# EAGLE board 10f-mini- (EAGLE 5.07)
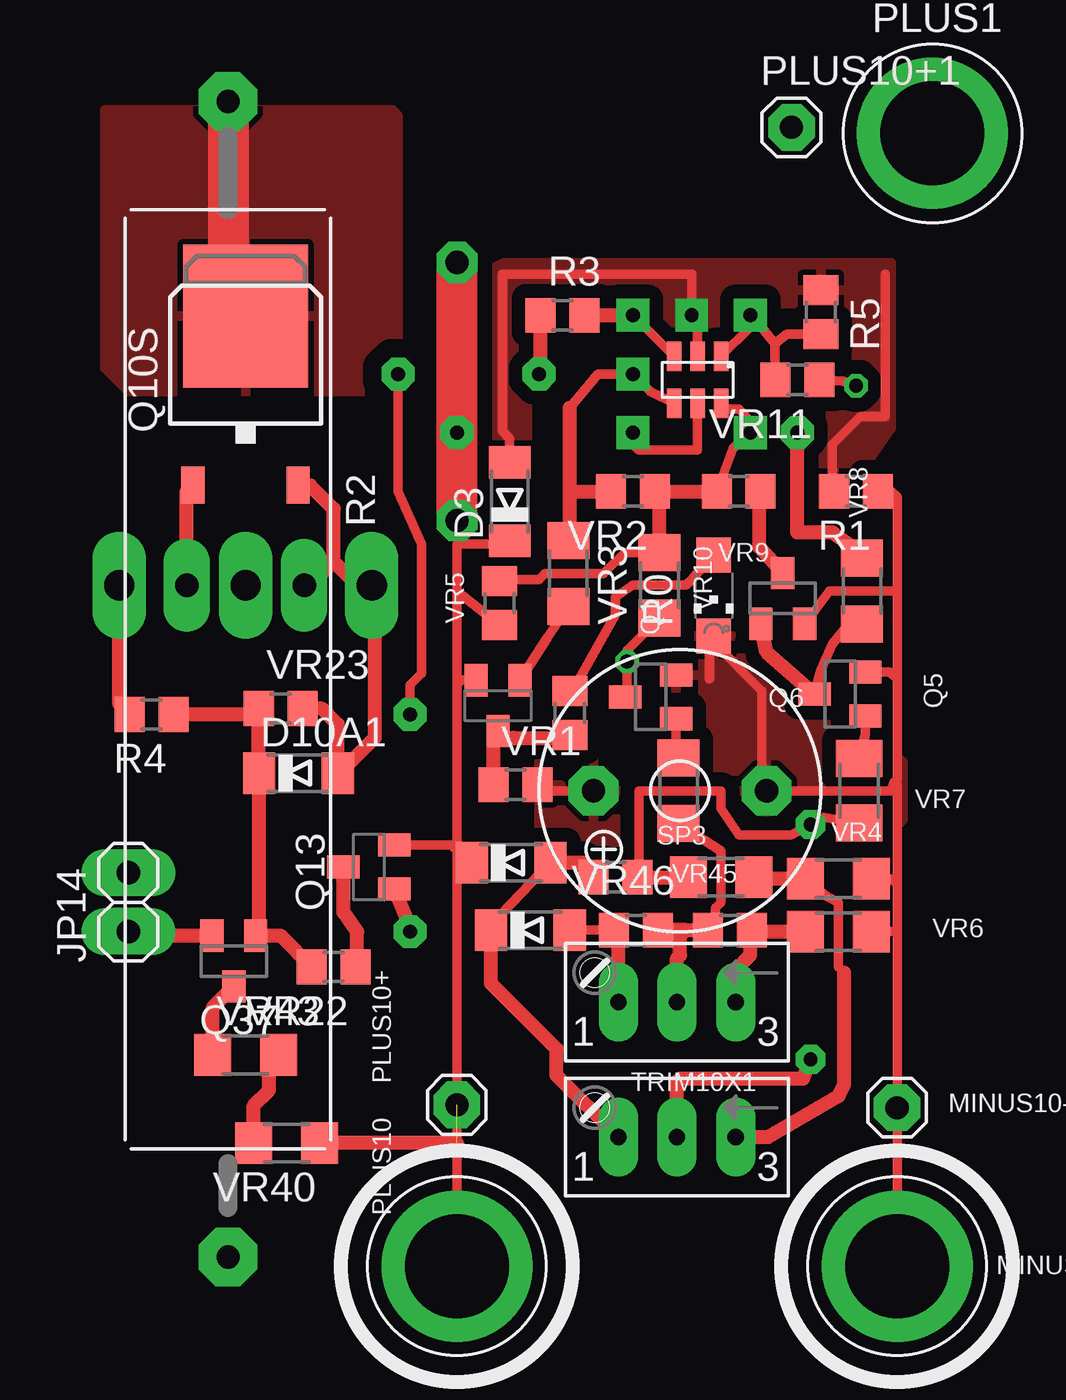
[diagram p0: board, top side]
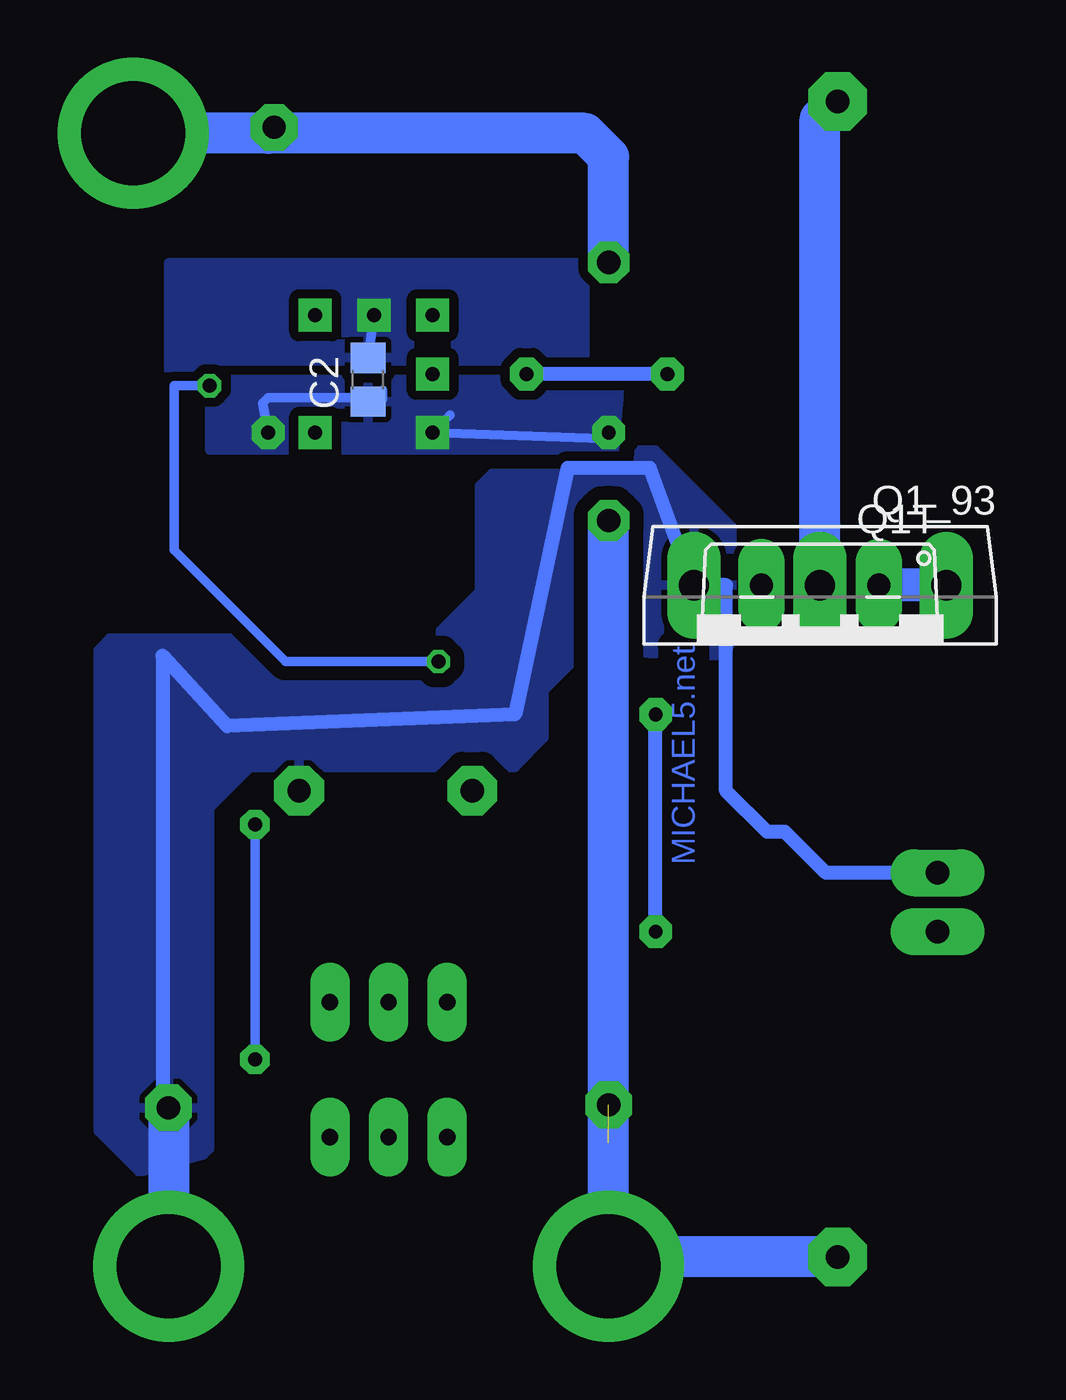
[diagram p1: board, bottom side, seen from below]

No outline drawn. Coordinates in mm, seen from the top.
Copper layers (1*16): Top 0.035mm / dielectric 1.5mm / Bottom 0.035mm
Design rules "default *": minimum track width 8mil, minimum drill 4mil, track to track 8mil, track to pad 8mil, pad to pad 8mil, via to via 8mil, smd to smd 8mil, copper to edge 40mil, drill to drill 8mil, minimum pad ring 20mil, minimum via ring 8mil, stop-mask expansion 4mil, vias tented up to drill 0mil, thermal gap 10mil

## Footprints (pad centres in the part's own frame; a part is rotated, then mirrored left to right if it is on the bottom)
C0805 = smd 1.3 x 1.5: 1 -0.95,0; 2 0.95,0
MINIMELF = smd 1.4 x 1.8: A 1.7,0; C -1.7,0
1X02 = drill 1.016 pad 1.676 long: 1 -1.27,0; 2 1.27,0
CHIPLED_1206 = smd 1.5 x 1.5: A 0,-1.75; C 0,1.75
1X4MM5 = drill 4.5 pad 6.35 round: 1 0,0
1X01 = drill 1 pad 1.676 octagon: 1 0,0
SOT23 = smd 1 x 1.4: 1 -0.95,-1.1; 2 0.95,-1.1; 3 0,1.1
SOT93V = drill 1.3 pad 1.676 long: B -5.461,-2.54; C 0,-2.54; E 5.461,-2.54
TO220AV = drill 1 pad 1.27 long: B -2.54,-2.54; C 0,-2.54; E 2.54,-2.54
D-PAK_TO252AA = smd 1 x 1.6: 1 -2.28,-4.8; 3 2.28,-4.8 | smd 5.4 x 6.2: 4 0,2.5
SOT23-BEC = smd 1 x 1.4: B -0.95,-1.1; C 0,1.1; E 0.95,-1.1
R1206 = smd 1.6 x 1.803: 1 -1.422,0; 2 1.422,0
R0805 = smd 1.3 x 1.5: 1 -0.95,0; 2 0.95,0
CERAM50 = drill 1 pad 2.54 octagon: 1 -25,0; 2 25,0
KSS1202 = drill 1 pad 2.159 octagon: + 3.75,0; - -3.75,0
S64W = drill 0.7 long: A 2.54,1.27; E -2.54,1.27; S 0,1.27
SOT23-6 = smd 0.635 x 1.27: 1 -1.016,-1.016; 2 0,-1.016; 3 1.016,-1.016; 4 1.016,1.016; 5 0,1.016; 6 -1.016,1.016
M1206 = smd 1.6 x 2: 1 -1.4,0; 2 1.4,0

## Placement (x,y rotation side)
C2  [C0805]  81.53,47.24 90 bottom
D3  [MINIMELF]  73.41,41.97 90 top
D10  [MINIMELF]  73.47,26.35 0 top
D10A  [MINIMELF]  74.3,23.43 0 top
D10A1  [MINIMELF]  64.26,30.23 0 top
JP14  [1X02]  56.9,24.64 90 top
LED10X  [CHIPLED_1206]  82.23,37.91 180 top
MINUS10  [1X4MM5]  90.17,8.89 0 top
MINUS10-  [1X01]  90.17,15.75 0 top
PLUS1  [1X4MM5]  91.69,57.91 0 top
PLUS10  [1X4MM5]  71.12,8.89 0 top
PLUS10+  [1X01]  71.12,15.88 0 top
PLUS10+1  [1X01]  85.6,58.17 0 top
Q1  BC847CSMD  [SOT23]  79.5,33.53 90 top
Q1_93  TIP142SOT93V  [SOT93V]  61.98,35.81 180 bottom
Q1T  TIP120TO220V  [TO220AV]  61.98,35.81 180 bottom
Q5  BC847CSMD  [SOT23]  87.69,33.66 90 top
Q6  BC847CSMD  [SOT23]  85.22,37.78 0 top
Q10S  TIP120  [D-PAK_TO252AA]  61.98,47.5 0 top
Q13  BC857CSMD  [SOT23-BEC]  67.31,26.16 90 top
Q14  BC857CSMD  [SOT23-BEC]  72.9,33.15 180 top
Q37  BC847CSMD  [SOT23]  61.47,22.1 180 top
R0  1/500u  [R1206]  80.71,29.46 90 top
R1  6k/2mA  [R0805]  88.39,42.42 180 top
R2  [CERAM50]  61.21,34.29 270 top
R3  4.4k/1m  [R0805]  75.69,50.04 0 top
R4  470/3m  [R0805]  57.91,32.77 180 top
R5  330k/10u  [R0805]  86.87,50.16 270 top
SP3  KSS1201  [KSS1202]  80.77,29.46 180 top
TRIM10X  [S64W]  80.64,21.59 180 top
TRIM10X1  [S64W]  80.64,15.75 180 top
U$1  PIC10F204OT  [SOT23-6]  81.53,47.24 180 top
VR1  1k/50m  [R0805]  73.66,29.72 0 top
VR2  0/na  [R0805]  78.74,42.42 180 top
VR3  10k/1m  [R1206]  75.95,38.86 270 top
VR4  680/5m  [R1206]  87.63,25.65 0 top
VR5  120k/30u  [R0805]  72.96,37.59 90 top
VR6  68/5m  [R1206]  87.63,23.37 0 top
VR7  3900/500u  [M1206]  88.52,29.46 270 top
VR8  47k/300u  [R1206]  88.65,38.1 270 top
VR9  10k/300u  [R0805]  83.31,42.42 0 top
VR10  15k/300u  [R1206]  79.88,38.35 90 top
VR11  47k/10u  [R0805]  85.85,47.24 180 top
VR14  20k/5m  [R0805]  76.01,32.83 90 top
VR22  750/0.5m  [R0805]  65.79,21.84 180 top
VR23  120k/100u  [R0805]  63.5,33.02 0 top
VR40  100/40m  [R1206]  63.75,14.22 180 top
VR43  100/40m  [R1206]  61.98,18.03 0 top
VR45  270/5m  [R0805]  77.98,25.72 180 top
VR46  220/5m  [R1206]  82.55,25.72 0 top
VR47  47/5m  [R0805]  82.93,23.43 180 top
VR48  56/5m  [R0805]  78.87,23.43 180 top

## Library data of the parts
C2 R2 = rcl
D3 D10 D10A D10A1 = diode
JP14 MINUS10 MINUS10- PLUS1 PLUS10 PLUS10+ PLUS10+1 = pinhead
LED10X = led
Q1 Q5 Q6 Q37 = transistor-npn
Q1_93 Q1T Q10S = transistor-power
Q13 Q14 = transistor-pnp
R0 R1 R3-R5 VR1-VR11 VR14 VR22 VR23 VR40 VR43 VR45-VR48 = rcl-2
SP3 = buzzer
TRIM10X TRIM10X1 = pot
U$1 = microchip-3

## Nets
B: R0.1 TRIM10X.S VR47.2 VR48.1
BUZZ+: SP3.+ VR1.2
GP3: U$1.4 VR2.2 VR3.1
MIN-: C2.1 D3.C D10.C PLUS1.1 PLUS10+1.1 PLUS10+.1 PLUS10.1 Q13.E Q14.E R2.2 U$1.5 VR5.1 VR8.1 VR40.1
N$1: R3.2 U$1.3
N$2: Q1.3 VR10.1 VR11.1
N$3: Q5.3 Q6.1 VR8.2
N$4: LED10X.A VR14.2
N$5: Q6.3 VR9.2
N$6: U$1.6 VR2.1 VR5.2 VR9.1 VR10.2
N$7: Q1.1 R0.2
N$8: Q14.C VR1.1 VR14.1
N$10: Q14.B VR3.2
N$14: D10A.A TRIM10X.A VR48.2
N$17: D10.A D10A.C TRIM10X1.A VR45.2
N$22: TRIM10X1.S VR7.2 VR45.1 VR46.1
N$23: Q13.B R3.1
N$24: TRIM10X1.E VR4.1 VR46.2
N$25: Q1_93.B Q1T.B Q10S.1 R4.2
N$128: TRIM10X.E VR6.1 VR47.1
N$136: JP14.1 Q37.2
N$138: R5.2 U$1.1 VR11.2
N$159: Q13.C VR22.1
N$163: VR40.2 VR43.2
N$164: Q37.3 VR43.1
N$168: Q5.1 VR7.1
N$179: D10A1.C Q37.1 R4.1 VR22.2 VR23.1
Q10C: Q1_93.C Q1T.C Q10S.4 R2.1
VSS: D10A1.A JP14.2 LED10X.C MINUS10-.1 MINUS10.1 Q1.2 Q1_93.E Q1T.E Q5.2 Q6.2 Q10S.3 R1.1 SP3.- VR4.2 VR6.2 VR23.2
VSS1: C2.2 D3.A R1.2 R5.1 U$1.2

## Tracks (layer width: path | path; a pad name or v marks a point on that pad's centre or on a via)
B
  Top 0.406: VR47.2 82.3,23.75 82.3,24.38 82.55,24.64 82.55,26.86 R0.1 | 80.64,22.23 80.77,22.35
  Top 0.61: 81.03,23.43 VR48.1 | 81.03,23.43 VR47.2 | TRIM10X.S 80.64,22.23 | 80.77,22.35 80.77,23.18 81.03,23.43
BUZZ+
  Top 0.406: SP3.+ 74.86,29.46 VR1.2
  pour Top (isolate 0.61): 75.44,31.24 78.99,31.24 79.5,30.73 79.5,27.18 79.25,26.92 75.44,26.92 74.68,27.69 74.68,30.73
GP3  (via drill 0.6 pad 1.42)
  Top 0.406: U$1.4 79.5,46.74 v78.74,47.5 77.22,47.5 76.01,46.04
  Top 0.61: 76.01,42.42 76.01,46.04 | 76.01,42.42 VR2.2 | 76.01,42.42 76.01,40.28 VR3.1
MIN-  (via drill 0.6 pad 1.42, 1 pad 1.78)  (1 unrouted)
  Top 0.406: PLUS10.1 71.12,14.22 71.12,26.35 | 71.12,26.35 D10.C | 71.12,34.04 71.12,26.92 70.93,27.11 70.87,27.11 | D3.C 72.53,40.13 71.12,40.13 71.12,37.59 | 71.12,34.04 71.12,37.59 | Q14.E 71.33,34.25 71.12,34.04 | VR5.1 71.18,38.04 71.12,37.59 | VR8.1 88.24,40.03 | U$1.5 81.53,44.2 78.99,44.2 78.74,44.45 v78.74,44.96 | 70.87,27.11 Q13.E | 71.12,26.35 71.12,26.86 70.87,27.11
  Top 0.61: 88.24,40.03 87.38,40.64 85.85,40.64 v85.85,44.96 | 71.12,14.22 VR40.1
  Top 1.778: v71.12,41.15 v71.12,44.96 v71.12,52.32
  Bottom 0.406: C2.1 80.91,46.8 80.91,46.4 81.03,46.4 81.03,46.48 85.85,46.48 86.11,46.23 v85.85,44.96 | 77.98,45.72 v78.74,44.96 71.37,44.7 v71.12,44.96
  Bottom 0.61: 71.01,9.29 71.12,9.4 PLUS10.1
  Bottom 1.778: 85.85,57.91 PLUS1.1 | 85.85,57.91 PLUS10+1.1 | 85.85,57.91 72.14,57.91 71.12,56.9 v71.12,52.32 | 71.12,9.4 v71.12,41.15 | R2.2 71.01,9.29
  pour Bottom (isolate 0.406): 70.61,47.24 88.39,47.24 88.39,44.2 70.87,44.2
N$1
  Top 0.406: 78.74,50.04 U$1.3
  Top 0.61: R3.2 78.74,50.04
N$2  (via drill 0.6, 0.6 pad 1.02)
  Top 0.406: VR11.1 87.82,47.18 v88.39,46.99 | 79.88,36.45 VR10.1 78.49,35.53 v78.49,35.05 78.49,33.61 Q1.3
  Bottom 0.406: v88.39,46.99 89.92,46.99 89.92,39.88 85.09,35.05 v78.49,35.05
N$3
  Top 0.406: VR8.2 88.49,37.19 87.38,35.81 86.87,34.69 Q5.3
  Top 0.61: Q6.1 84.52,35.47 Q5.3
N$4
  Top 0.406: VR14.2 76.39,34.23 77.98,37.08 77.98,37.85 78.74,38.35 81.03,38.35 81.28,38.61 81.79,39.22 LED10X.A
N$5
  Top 0.406: 84.58,42.23 VR9.2
  Top 0.61: Q6.3 84.2,40.01 84.2,42.16 84.58,42.23
N$6
  Top 0.406: VR9.1 83.06,44.26 83.82,44.96 83.82,45.47 83.31,45.97 82.8,45.97 U$1.6 | VR10.2 78.38,39.78 77.47,38.86 74.93,38.86 74.68,38.61 73.66,38.61 VR5.2 | 79.88,42.23 VR2.1
  Top 0.61: VR2.1 VR9.1 | VR10.2 79.88,42.23
N$7
  Top 0.406: Q1.1 80.6,30.99 R0.2
N$8
  Top 0.406: 75.95,31.75 76.33,32.13 VR14.1 | 73.55,31.75 Q14.C 72.71,31.86
  Top 0.61: 73.55,31.75 75.95,31.75 | VR1.1 72.71,31.86
N$9  (via drill 0.6 pad 1.42)
  other vias: 83.82,44.96
N$10
  Top 0.406: Q14.B 75.04,36.09 VR3.2
N$11  (via drill 0.6 pad 1.42)
  other vias: 83.82,50.04
N$14
  Top 0.406: 78.11,23.37 VR48.2 D10A.A
  Top 0.61: TRIM10X.A 78.11,23.37
N$17
  Top 0.406: 76.58,26.35 VR45.2 | D10A.C 72.59,23.65 D10.A
  Top 0.61: D10.A 76.58,26.35 | D10A.C 72.59,21.13 75.44,18.29 75.44,17.14 TRIM10X1.A
N$22  (via drill 0.6 pad 1.27)
  Top 0.406: VR45.1 78.99,25.72 78.99,29.46 82.55,29.46 82.55,28.7 83.31,27.56 85.6,27.56 v86.42,28 86.99,28.32 VR7.2 | 80.64,16.89 80.77,17.02
  Top 0.61: 78.99,25.72 VR46.1 | TRIM10X1.S 80.64,16.89 | 80.77,17.02 86.11,17.02 v86.42,17.84
  Bottom 0.406: v86.42,17.84 v86.42,28
N$23  (via drill 0.6 pad 1.42)
  Top 0.406: v69.09,32.77 69.09,34.04 69.6,34.54 69.6,40.13 68.58,42.42 v68.58,47.5
  Top 0.61: R3.1 74.74,47.82 v74.68,47.5 | Q13.B 68.92,23.96 v69.09,23.37
  Bottom 0.406: v68.58,47.5 69.09,47.5
  Bottom 0.61: 68.58,47.75 69.09,47.5 v74.68,47.5 | v69.09,23.37 v69.09,32.77
N$24
  Top 0.406: 87.88,21.59 87.63,21.84 87.63,24.64 87.12,24.89 86.46,25.4 VR4.1 | 84.03,25.65 VR46.2
  Top 0.61: TRIM10X1.E 84.58,14.48 87.63,16.26 87.88,16.76 87.88,21.59 | VR4.1 84.03,25.65
N$25
  Top 0.61: Q1_93.B 56.52,33.21 R4.2 | Q1T.B 59.44,42.44 Q10S.1
  Bottom 1.422: Q1_93.B Q1T.B
N$128
  Top 0.406: 83.82,23.37 VR47.1 83.82,23.37
  Top 0.61: TRIM10X.E 83.19,21.72 83.82,22.35 83.82,23.37 | 83.82,23.37 VR6.1
N$136
  Top 0.61: Q37.2 57.07,23.2 JP14.1
N$138
  Top 0.406: VR11.2 84.89,48.82 | 84.89,48.82 84.14,49.72 83.82,50.04 83.82,49.53 U$1.1 | R5.2 85.39,49.22 84.89,48.82
N$159
  Top 0.61: Q13.C 66.21,24.21 66.8,23.37 66.8,21.91 VR22.1
N$163
  Top 0.61: VR40.2 62.33,15.85 62.99,16.51 62.99,17.63 VR43.2
N$164
  Top 0.61: VR43.1 60.55,20.08 Q37.3
N$168
  Top 0.406: Q5.1 88.79,31.9 VR7.1
N$179
  Top 0.61: R4.1 62.3,32.77 VR23.1 D10A1.C 62.56,23.34 Q37.1 63.48,23.2 VR22.2
Q10C
  Top 1.422: 62.23,49.28 62.23,49.74 Q10S.4
  Top 1.778: R2.1 61.21,50.29 62.23,49.28
  Bottom 1.778: Q1_93.C 61.98,58.53 R2.1
  pour Top (isolate 0.813): 55.88,58.93 68.33,58.93 68.58,58.67 68.58,47.5 67.82,46.74 56.9,46.74 55.88,47.75
VDF  (via drill 0.6 pad 1.42)
  other vias: 78.74,50.04
VSS
  Top 0.406: MINUS10.1 90.17,23.37 | 90.17,23.37 90.17,25.4 | VR4.2 89.92,25.65 90.17,25.4 | 90.17,23.37 VR6.2 | 90.04,29.84 90.17,29.72 90.17,25.4 | 90.04,29.84 89.92,29.46 SP3.- 84.33,29.66 84.33,33.78 82.23,35.88 LED10X.C 82.04,35.97 82.04,34.29 | Q5.2 89.86,34.6 90.17,34.29 | 90.17,34.29 90.17,29.97 90.04,29.84 | R1.1 89.92,42.42 90.17,42.16 90.17,38.1 | 90.17,34.29 90.17,38.1 | Q6.2 87.23,38.1 90.17,38.1
  Top 0.61: VR23.2 65.28,33.02 65.96,32.34 D10A1.A 66.04,30.23 67.56,31.75 67.56,38.23 Q1_93.E 66.8,38.35 65.79,39.37 | Q1T.E 64.77,38.35 65.79,39.37 | 65.79,39.37 65.79,41.66 64.77,42.67 64.28,42.67 Q10S.3
  Bottom 0.61: MINUS10-.1 90.42,16 90.42,35.31 87.63,32.26 75.18,32.77 72.9,43.43 69.34,43.43 67.44,38.23 Q1_93.E 66.04,38.35 66.04,29.46 64.26,27.69 63.5,27.69 61.72,25.91 JP14.2
  Bottom 1.778: MINUS10-.1 MINUS10.1
  pour Top (isolate 0.61): 81.53,36.83 81.53,34.8 80.52,33.78 80.52,32 84.58,27.94 90.17,27.94 90.42,28.19 90.42,30.73 89.66,31.5 87.12,31.5 87.12,34.29 85.6,35.05
  pour Bottom (isolate 0.61, rank 2): 91.44,12.95 93.22,14.73 93.22,35.56 92.71,36.07 78.74,36.07 76.71,38.1 76.71,42.67 75.18,44.2 69.09,44.2 65.79,40.89 65.79,36.07 66.04,35.31 68.83,35.31 70.36,35.56 72.14,35.56 73.91,33.78 73.91,31.75 75.18,30.48 86.61,30.48 88.39,28.7 88.39,13.97 88.65,13.72
VSS1  (via drill 0.6 pad 1.42)
  Top 0.406: 89.66,51.82 89.66,45.66 88.58,45.66 87.38,44.45 87.38,42.61 | U$1.2 81.53,49.47 v81.28,50.04 81.28,51.82 73.09,51.82 73.09,45.02 73.41,44.7 D3.A | R5.1 87.12,51.24
  Top 0.61: R1.2 87.38,42.61
  Bottom 0.406: v81.28,50.04 C2.2
  pour Bottom (isolate 0.406, rank 2): 72.14,52.32 90.17,52.32 90.17,47.5 72.14,47.5
  pour Top (isolate 0.61): 72.64,44.45 72.64,52.07 73.15,52.32 89.92,52.32 89.92,45.15 88.39,42.93 86.61,42.93 86.61,48.77 87.38,49.53 87.38,50.04 86.87,50.55 83.31,50.55 82.3,49.53 80.26,49.53 80.26,49.78 79.5,50.55 74.68,50.55 74.17,50.04 74.17,44.2

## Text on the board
Bottom: MICHAEL5.net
